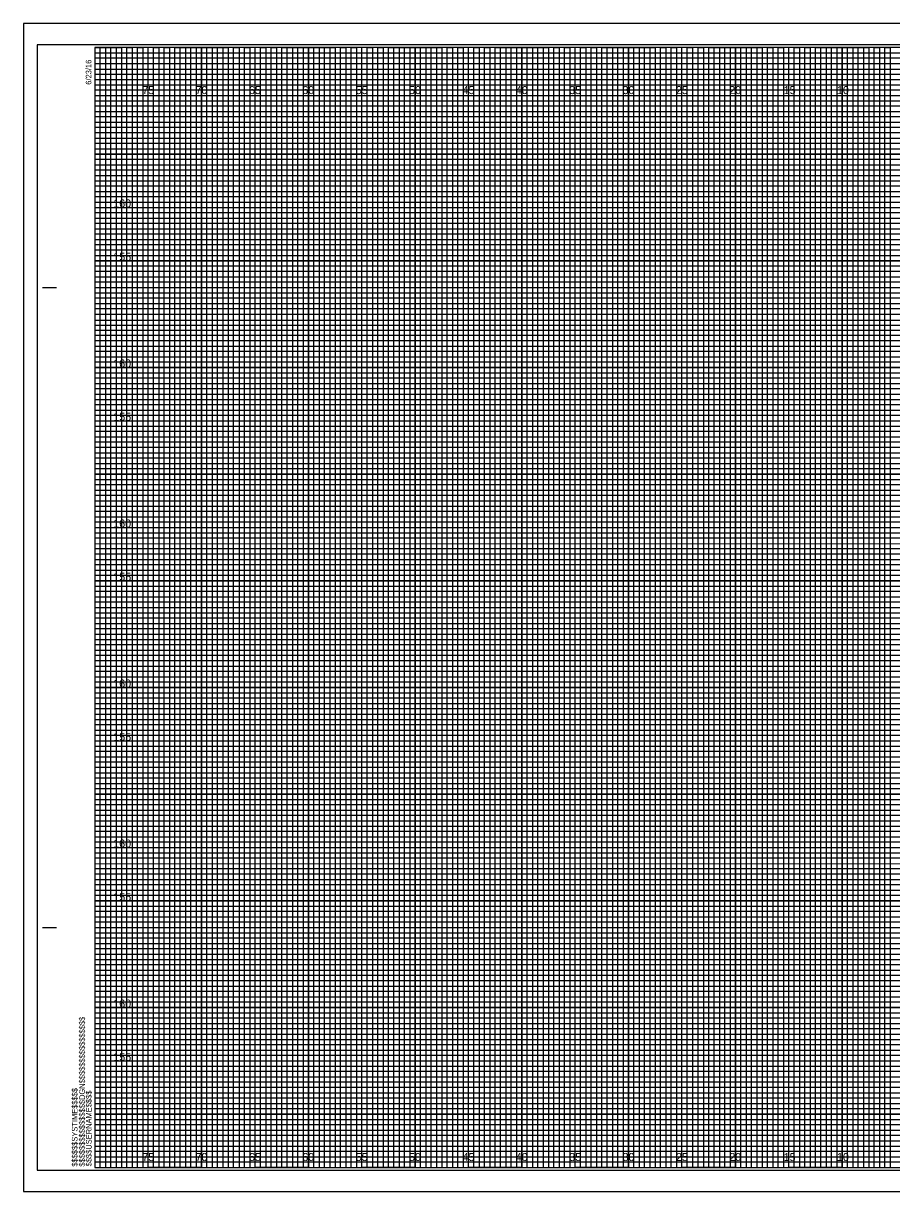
# Model space of a CAD drawing. Extents: x -7 to 162, y 328 to 437.
# Drawn here: x -6.7 to 74.6, y 327.7 to 437.2 of the extents above; entities that cross this region are included whole.
import ezdxf

# ---------------------------------------------------------------- set-up
doc = ezdxf.new("R2010")
doc.units = 0
for name, color, linetype in [('Prop CMT Conc Surface', 7, 'Continuous'), ('Prop CMT Pvmt Course 1', 7, 'Continuous'), ('Prop CMT Pvmt Surface Shoulder', 7, 'Continuous'), ('Prop CMT Pvmt Wedge Surface 3', 7, 'Continuous'), ('Prop CMT Shld Paved Course 1', 7, 'Continuous'), ('Prop CMT Shld Paved Course 2', 7, 'Continuous'), ('Prop CMT Slope Grass', 7, 'Continuous'), ('Prop XS Ditch Standard Text', 7, 'Continuous'), ('Prop XS Hydro Elevations', 7, 'Continuous'), ('Prop XS SE Text', 7, 'Continuous'), ('Prop XS Side Slope Text', 7, 'Continuous')]:
    doc.layers.add(name, color=color, linetype=linetype)

msp = doc.modelspace()

# ---------------------------------------------------------------- linework, layer by layer
at = {"layer": 'Prop CMT Conc Surface'}
for points in [[(0, 435), (2.5, 435), (2.5, 330), (7.5, 330), (7.5, 435), (12.5, 435), (12.5, 330), (17.5, 330), (17.5, 435), (22.5, 435), (22.5, 330), (27.5, 330), (27.5, 435), (32.5, 435), (32.5, 330), (37.5, 330), (37.5, 435), (42.5, 435), (42.5, 330), (47.5, 330), (47.5, 435), (52.5, 435), (52.5, 330), (57.5, 330), (57.5, 435), (62.5, 435), (62.5, 330), (67.5, 330), (67.5, 435), (72.5, 435), (72.5, 330), (77.5, 330)], [(0, 432.5), (137.5, 432.5)], [(0, 422.5), (160, 422.5), (160, 427.5), (0, 427.5)], [(0, 412.5), (160, 412.5), (160, 417.5), (0, 417.5)], [(0, 402.5), (160, 402.5), (160, 407.5), (0, 407.5)], [(0, 392.5), (160, 392.5), (160, 397.5), (0, 397.5)], [(0, 382.5), (160, 382.5), (160, 387.5), (0, 387.5)], [(0, 372.5), (160, 372.5), (160, 377.5), (0, 377.5)], [(0, 362.5), (160, 362.5), (160, 367.5), (0, 367.5)], [(0, 352.5), (160, 352.5), (160, 357.5), (0, 357.5)], [(0, 342.5), (160, 342.5), (160, 347.5), (0, 347.5)], [(0, 332.5), (160, 332.5), (160, 337.5), (0, 337.5)]]:
    msp.add_lwpolyline(points, dxfattribs=at)
at = {"layer": 'Prop CMT Pvmt Course 1'}
for p, q in [((5, 435), (0, 435)), ((5, 330), (5, 435)), ((15, 435), (10, 435)), ((10, 435), (10, 330)), ((15, 330), (15, 435)), ((25, 435), (20, 435)), ((20, 435), (20, 330)), ((25, 330), (25, 435)), ((35, 435), (30, 435)), ((30, 435), (30, 330)), ((35, 330), (35, 435)), ((45, 435), (40, 435)), ((40, 435), (40, 330)), ((45, 330), (45, 435)), ((55, 435), (50, 435)), ((50, 435), (50, 330)), ((55, 330), (55, 435)), ((65, 435), (60, 435)), ((60, 435), (60, 330)), ((65, 330), (65, 435)), ((75, 435), (70, 435)), ((70, 435), (70, 330)), ((10, 330), (5, 330)), ((20, 330), (15, 330)), ((30, 330), (25, 330)), ((40, 330), (35, 330)), ((50, 330), (45, 330)), ((60, 330), (55, 330)), ((70, 330), (65, 330))]:
    msp.add_line(p, q, dxfattribs=at)
for points in [[(0, 430), (160, 430), (160, 425), (0, 425)], [(0, 420), (160, 420), (160, 415), (0, 415)], [(0, 410), (160, 410), (160, 405), (0, 405)], [(0, 400), (160, 400), (160, 395), (0, 395)], [(0, 390), (160, 390), (160, 385), (0, 385)], [(0, 380), (160, 380), (160, 375), (0, 375)], [(0, 370), (160, 370), (160, 365), (0, 365)], [(0, 360), (160, 360), (160, 355), (0, 355)], [(0, 350), (160, 350), (160, 345), (0, 345)], [(0, 340), (160, 340), (160, 335), (0, 335)]]:
    msp.add_lwpolyline(points, dxfattribs=at)
at = {"layer": 'Prop CMT Pvmt Surface Shoulder'}
msp.add_lwpolyline([(-6.7, 327.75), (161.65, 327.75), (161.65, 437.25), (-6.7, 437.25)], close=True, dxfattribs=at)
at = {"layer": 'Prop CMT Shld Paved Course 1'}
for p, q in [((-4.9, 412.5), (-3.65, 412.5)), ((-4.85, 412.5), (-3.6, 412.5)), ((-4.9, 352.5), (-3.65, 352.5)), ((-4.85, 352.5), (-3.6, 352.5)), ((0, 330), (0, 330)), ((0, 330), (0, 330)), ((0, 330), (0, 330)), ((0, 330), (0, 330)), ((0, 330), (0, 330)), ((0, 330), (0, 330)), ((0, 330), (0, 330))]:
    msp.add_line(p, q, dxfattribs=at)
msp.add_lwpolyline([(160, 435), (0, 435), (0, 330), (160, 330)], close=True, dxfattribs=at)
at = {"layer": 'Prop CMT Shld Paved Course 2'}
for points in [[(0, 330), (0.5, 330), (0.5, 435), (1, 435), (1, 330)], [(1, 330), (1.5, 330), (1.5, 435), (2, 435), (2, 330)], [(2.5, 330), (3, 330), (3, 435), (3.5, 435), (3.5, 330)], [(3.5, 330), (4, 330), (4, 435), (4.5, 435), (4.5, 330)], [(5, 330), (5.5, 330), (5.5, 435), (6, 435), (6, 330)], [(6, 330), (6.5, 330), (6.5, 435), (7, 435), (7, 330)], [(7.5, 330), (8, 330), (8, 435), (8.5, 435), (8.5, 330)], [(8.5, 330), (9, 330), (9, 435), (9.5, 435), (9.5, 330)], [(10, 330), (10.5, 330), (10.5, 435), (11, 435), (11, 330)], [(11, 330), (11.5, 330), (11.5, 435), (12, 435), (12, 330)], [(12.5, 330), (13, 330), (13, 435), (13.5, 435), (13.5, 330)], [(13.5, 330), (14, 330), (14, 435), (14.5, 435), (14.5, 330)], [(15, 330), (15.5, 330), (15.5, 435), (16, 435), (16, 330)], [(16, 330), (16.5, 330), (16.5, 435), (17, 435), (17, 330)], [(17.5, 330), (18, 330), (18, 435), (18.5, 435), (18.5, 330)], [(18.5, 330), (19, 330), (19, 435), (19.5, 435), (19.5, 330)], [(20, 330), (20.5, 330), (20.5, 435), (21, 435), (21, 330)], [(21, 330), (21.5, 330), (21.5, 435), (22, 435), (22, 330)], [(22.5, 330), (23, 330), (23, 435), (23.5, 435), (23.5, 330)], [(23.5, 330), (24, 330), (24, 435), (24.5, 435), (24.5, 330)], [(25, 330), (25.5, 330), (25.5, 435), (26, 435), (26, 330)], [(26, 330), (26.5, 330), (26.5, 435), (27, 435), (27, 330)], [(27.5, 330), (28, 330), (28, 435), (28.5, 435), (28.5, 330)], [(28.5, 330), (29, 330), (29, 435), (29.5, 435), (29.5, 330)], [(30, 330), (30.5, 330), (30.5, 435), (31, 435), (31, 330)], [(31, 330), (31.5, 330), (31.5, 435), (32, 435), (32, 330)], [(32.5, 330), (33, 330), (33, 435), (33.5, 435), (33.5, 330)], [(33.5, 330), (34, 330), (34, 435), (34.5, 435), (34.5, 330)], [(35, 330), (35.5, 330), (35.5, 435), (36, 435), (36, 330)], [(36, 330), (36.5, 330), (36.5, 435), (37, 435), (37, 330)], [(37.5, 330), (38, 330), (38, 435), (38.5, 435), (38.5, 330)], [(38.5, 330), (39, 330), (39, 435), (39.5, 435), (39.5, 330)], [(40, 330), (40.5, 330), (40.5, 435), (41, 435), (41, 330)], [(41, 330), (41.5, 330), (41.5, 435), (42, 435), (42, 330)], [(42.5, 330), (43, 330), (43, 435), (43.5, 435), (43.5, 330)], [(43.5, 330), (44, 330), (44, 435), (44.5, 435), (44.5, 330)], [(45, 330), (45.5, 330), (45.5, 435), (46, 435), (46, 330)], [(46, 330), (46.5, 330), (46.5, 435), (47, 435), (47, 330)], [(47.5, 330), (48, 330), (48, 435), (48.5, 435), (48.5, 330)], [(48.5, 330), (49, 330), (49, 435), (49.5, 435), (49.5, 330)], [(50, 330), (50.5, 330), (50.5, 435), (51, 435), (51, 330)], [(51, 330), (51.5, 330), (51.5, 435), (52, 435), (52, 330)], [(52.5, 330), (53, 330), (53, 435), (53.5, 435), (53.5, 330)], [(53.5, 330), (54, 330), (54, 435), (54.5, 435), (54.5, 330)], [(55, 330), (55.5, 330), (55.5, 435), (56, 435), (56, 330)], [(56, 330), (56.5, 330), (56.5, 435), (57, 435), (57, 330)], [(57.5, 330), (58, 330), (58, 435), (58.5, 435), (58.5, 330)], [(58.5, 330), (59, 330), (59, 435), (59.5, 435), (59.5, 330)], [(60, 330), (60.5, 330), (60.5, 435), (61, 435), (61, 330)], [(61, 330), (61.5, 330), (61.5, 435), (62, 435), (62, 330)], [(62.5, 330), (63, 330), (63, 435), (63.5, 435), (63.5, 330)], [(63.5, 330), (64, 330), (64, 435), (64.5, 435), (64.5, 330)], [(65, 330), (65.5, 330), (65.5, 435), (66, 435), (66, 330)], [(66, 330), (66.5, 330), (66.5, 435), (67, 435), (67, 330)], [(67.5, 330), (68, 330), (68, 435), (68.5, 435), (68.5, 330)], [(68.5, 330), (69, 330), (69, 435), (69.5, 435), (69.5, 330)], [(70, 330), (70.5, 330), (70.5, 435), (71, 435), (71, 330)], [(71, 330), (71.5, 330), (71.5, 435), (72, 435), (72, 330)], [(72.5, 330), (73, 330), (73, 435), (73.5, 435), (73.5, 330)], [(73.5, 330), (74, 330), (74, 435), (74.5, 435), (74.5, 330)]]:
    msp.add_lwpolyline(points, dxfattribs=at)
at = {"layer": 'Prop CMT Slope Grass'}
for p, q in [((0, 434.5), (130, 434.5)), ((130, 433.99), (0, 433.99)), ((0, 433.99), (0, 433.5)), ((0, 433.5), (130, 433.5)), ((130, 432.94), (0, 432.94)), ((0, 432.94), (0, 432)), ((0, 432), (160, 432))]:
    msp.add_line(p, q, dxfattribs=at)
for points in [[(0, 431.5), (135, 431.5), (160, 431.5), (160, 431), (0, 431)], [(0, 430.5), (160, 430.5), (160, 429.5), (0, 429.5)], [(0, 429), (160, 429), (160, 428.5), (0, 428.49)], [(0, 428), (160, 428), (160, 427), (0, 427)], [(0, 426.5), (160, 426.5), (160, 426), (0, 426)], [(0, 425.5), (160, 425.5), (160, 424.5), (0, 424.5)], [(0, 424), (160, 424), (160, 423.5), (0, 423.5)], [(0, 423), (160, 423), (160, 422), (0, 422)], [(0, 421.5), (160, 421.5), (160, 421), (0, 421)], [(0, 420.5), (160, 420.5), (160, 419.5), (0, 419.5)], [(0, 419), (160, 419), (160, 418.5), (0, 418.5)], [(0, 418), (160, 418), (160, 416.98), (160, 416.5), (160, 416), (0, 416)], [(0, 417), (160, 417), (160, 416.5), (0, 416.5)], [(0, 415.5), (160, 415.5), (160, 414.5), (0, 414.51)], [(0, 414.51), (160, 414.5), (160, 414), (0, 414)], [(0, 413.5), (160, 413.5), (160, 413), (0, 413)], [(0, 412), (160, 412), (160, 411.5), (0, 411.5)], [(0, 411), (160, 411), (160, 410.5), (0, 410.5)], [(-0.04, 409.44), (160, 409.44), (160, 408.94), (-0.04, 408.94)], [(0, 408.5), (160, 408.5), (160, 408), (0, 408)], [(0, 407), (160, 407), (160, 406.5), (0, 406.5)], [(0, 406), (160, 406), (160, 405.5), (0, 405.5)], [(0, 404.5), (160, 404.5), (160, 404), (0, 404)], [(0, 403.5), (160, 403.5), (160, 403), (0, 403)], [(0, 402), (160, 402), (160, 401.5), (0, 401.5)], [(0, 401), (160, 401), (160, 400.5), (0, 400.5)], [(0, 399.5), (160, 399.5), (160, 398.99), (0, 399)], [(0, 398.5), (160, 398.5), (160, 398), (0, 398)], [(0, 397), (160, 397), (160, 396.5), (0, 396.5)], [(0, 396), (160, 396), (160, 395.5), (0, 395.5)], [(0, 394.5), (160, 394.5), (160, 394), (0, 394)], [(0, 393.5), (160, 393.5), (160, 393), (0, 393)], [(0, 392), (160, 392), (160, 391.5), (0, 391.5)], [(0, 391), (160, 391), (160, 390.5), (0, 390.5)], [(0, 389.5), (160, 389.5), (160, 389), (0, 389)], [(0, 388.5), (160.03, 388.45), (160, 388), (0, 388)], [(0, 387), (160, 387), (160, 386.5), (0, 386.5)], [(0, 386), (160, 386), (160, 385.5), (0, 385.5)], [(0, 384.5), (160, 384.5), (160, 384), (0, 384)], [(0, 383.5), (160, 383.5), (160, 383), (0, 383)], [(0, 382), (160, 382), (160, 381.5), (0, 381.5)], [(0, 381), (160, 381), (160, 380.5), (0, 380.5)], [(0, 379.5), (160, 379.5), (160, 379), (0, 379)], [(0, 378.5), (160, 378.5), (160, 378), (0, 378)], [(0, 377), (160, 377), (160, 376.5), (0, 376.5)], [(0, 376), (160, 376), (160, 375.5), (0, 375.5)], [(0, 374.5), (160, 374.5), (160, 374), (0, 374)], [(0, 373.5), (160, 373.5), (160, 373), (0, 373)], [(0, 372), (160, 372), (160, 371.5), (0, 371.5)], [(0, 371), (160, 371), (160, 370.5), (0, 370.5)], [(0, 369.5), (160, 369.5), (160, 368.99), (0, 369)], [(0, 368.5), (160, 368.5), (160, 368), (0, 368)], [(0, 367), (160, 367), (160, 366.5), (0, 366.5)], [(0, 366), (160, 366), (160, 365.5), (0, 365.5)], [(0, 364.5), (160, 364.5), (160, 364), (0, 364)], [(0, 363.5), (160, 363.5), (160, 363), (0, 363)], [(0, 362), (160, 362), (160, 361.5), (0, 361.5)], [(0, 361), (160, 361), (160, 360.5), (0, 360.5)], [(0, 359.5), (160, 359.5), (160, 359), (0, 359)], [(0, 358.5), (160.03, 358.45), (160, 358), (0, 358)], [(0, 357), (160, 357), (160, 356.5), (0, 356.5)], [(0, 356), (160, 356), (160, 355.5), (0, 355.5)], [(0, 354.5), (160, 354.5), (160, 354), (0, 354)], [(0, 353.5), (160, 353.5), (160, 353), (0, 353)], [(0, 352), (160, 352), (160, 351.5), (0, 351.5)], [(0, 351), (160, 351), (160, 350.5), (0, 350.5)], [(0, 349.5), (160, 349.5), (160, 349), (0, 349)], [(0, 348.5), (160, 348.5), (160, 348), (0, 348)], [(0, 347), (160, 347), (160, 346.5), (0, 346.5)], [(0, 346), (160, 346), (160, 345.5), (0, 345.5)], [(0, 344.5), (160, 344.5), (160, 344), (0, 344)], [(0, 343.5), (160, 343.5), (160, 343), (0, 343)], [(0, 342), (160, 342), (160, 341.5), (0, 341.5)], [(0, 341), (160, 341), (160, 340.5), (0, 340.5)], [(0, 339.5), (160, 339.5), (160, 339), (0, 339)], [(0, 338.5), (160, 338.5), (160, 338), (0, 338)], [(0, 337), (160, 337), (160, 336.5), (0, 336.5)], [(0, 336), (160, 336), (160, 335.5), (0, 335.5)], [(0, 334.5), (160, 334.5), (160, 334), (0, 334)], [(0, 333.5), (160, 333.5), (160, 333), (0, 333)], [(0, 332), (160, 332), (160, 331.5), (0, 331.5)], [(0, 331), (160, 331), (160, 330.5), (0, 330.5)]]:
    msp.add_lwpolyline(points, dxfattribs=at)
at = {"layer": 'Prop XS Hydro Elevations'}
for p, q in [((161.65, 437.25), (-6.7, 437.25)), ((-6.7, 437.25), (-6.7, 327.75)), ((-6.7, 327.75), (161.65, 327.75))]:
    msp.add_line(p, q, dxfattribs=at)
at = {"layer": 'Prop XS SE Text'}
msp.add_lwpolyline([(-5.4, 329.75), (161.2, 329.75), (161.2, 435.25), (-5.4, 435.25)], close=True, dxfattribs=at)
at = {"layer": 'Prop XS Side Slope Text'}
for p, q in [((5, 330), (5, 435)), ((10, 330), (10, 435)), ((15, 330), (15, 435)), ((20, 330), (20, 435)), ((25, 330), (25, 435)), ((30, 330), (30, 435)), ((35, 330), (35, 435)), ((40, 330), (40, 435)), ((45, 330), (45, 435)), ((50, 330), (50, 435)), ((55, 330), (55, 435)), ((60, 330), (60, 435)), ((65, 330), (65, 435)), ((70, 330), (70, 435)), ((0, 430), (160, 430)), ((0, 425), (160, 425)), ((0, 420), (160, 420)), ((0, 415), (160, 415)), ((0, 410), (160, 410)), ((0, 405), (160, 405)), ((0, 400), (160, 400)), ((0, 395), (160, 395)), ((0, 390), (160, 390)), ((0, 385), (160, 385)), ((0, 380), (160, 380)), ((0, 375), (160, 375)), ((0, 370), (160, 370)), ((0, 365), (160, 365)), ((0, 360), (160, 360)), ((0, 355), (160, 355)), ((0, 350), (160, 350)), ((0, 345), (160, 345)), ((0, 340), (160, 340)), ((0, 335), (160, 335))]:
    msp.add_line(p, q, dxfattribs=at)

# ---------------------------------------------------------------- texts
at = {"layer": 'Prop CMT Pvmt Wedge Surface 3'}
for s, p in [('75', (4.44, 430.62)), ('70', (9.43, 430.62)), ('65', (14.44, 430.62)), ('60', (19.43, 430.62)), ('55', (24.44, 430.62)), ('50', (29.43, 430.62)), ('45', (34.44, 430.62)), ('40', (39.43, 430.62)), ('35', (44.44, 430.62)), ('30', (49.43, 430.62)), ('25', (54.44, 430.62)), ('20', (59.43, 430.62)), ('15', (64.53, 430.62)), ('10', (69.52, 430.62)), ('75', (4.44, 330.62)), ('70', (9.43, 330.62)), ('65', (14.44, 330.62)), ('60', (19.43, 330.62)), ('55', (24.44, 330.62)), ('50', (29.43, 330.62)), ('45', (34.44, 330.62)), ('40', (39.43, 330.62)), ('35', (44.44, 330.62)), ('30', (49.43, 330.62)), ('25', (54.44, 330.62)), ('20', (59.43, 330.62)), ('15', (64.53, 330.62)), ('10', (69.52, 330.62))]:
    msp.add_text(s, height=0.75, dxfattribs=at).set_placement(p)
at = {"layer": 'Prop CMT Shld Paved Course 1'}
for s, p in [('6/23/16', (-0.33, 431.5)), ('$$$$$$$$$$$$$$$$DGN$$$$$$$$$$$$$$$$', (-0.94, 330.09)), ('$$$$$$SYSTIME$$$$$', (-1.63, 330.09)), ('$$$$USERNAME$$$$', (-0.31, 330.12))]:
    msp.add_text(s, height=0.525, rotation=90, dxfattribs=at).set_placement(p)
at = {"layer": 'Prop XS Ditch Standard Text'}
for s, p in [('160', (1.72, 420)), ('155', (1.73, 415)), ('160', (1.72, 405)), ('155', (1.73, 400)), ('160', (1.72, 390)), ('155', (1.73, 385)), ('160', (1.72, 375)), ('155', (1.73, 370)), ('160', (1.72, 360)), ('155', (1.73, 355)), ('160', (1.72, 345)), ('155', (1.73, 340))]:
    msp.add_text(s, height=0.75, dxfattribs=at).set_placement(p)

doc.saveas('drawing.dxf')
